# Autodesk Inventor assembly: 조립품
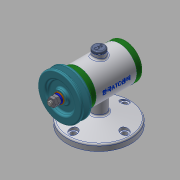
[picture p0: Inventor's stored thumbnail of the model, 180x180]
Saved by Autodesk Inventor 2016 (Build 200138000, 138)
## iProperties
Created: 2018-12
Part Number: 조립품
Material: 일반
Document SubType Name: Assembly
Designer: 605-08
Author: 605-08
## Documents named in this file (15)
- C:\Users\605-08\Desktop\481207V1006\조립품.iam
- C:\Users\605-08\Desktop\481207V1006\본체.ipt
- C:\Users\605-08\Desktop\481207V1006\베어링 15 x 32 x 9.ipt
- C:\Users\605-08\Desktop\481207V1006\축.ipt
- C:\Users\605-08\Desktop\481207V1006\앞커버.ipt
- C:\Users\605-08\Desktop\481207V1006\뒤커버.ipt
- C:\Users\605-08\Desktop\481207V1006\오일 실 15 25 7.ipt
- C:\Users\605-08\Desktop\481207V1006\키 3 x 3 x 12.ipt
- C:\Users\605-08\Desktop\481207V1006\고무캡.ipt
- C:\Users\605-08\Desktop\481207V1006\볼트 M4 x 12.ipt
- C:\Users\605-08\Desktop\481207V1006\V벨트풀리.ipt
- C:\Users\605-08\Desktop\481207V1006\스프링와셔 8.ipt
- C:\Users\605-08\Desktop\481207V1006\와셔 8x17.ipt
- C:\Users\605-08\Desktop\481207V1006\너트 M8.ipt
- 너트 M8.ipt
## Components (2 placed, 2 different names)
1. 고무캡:1
2. V벨트풀리:1
